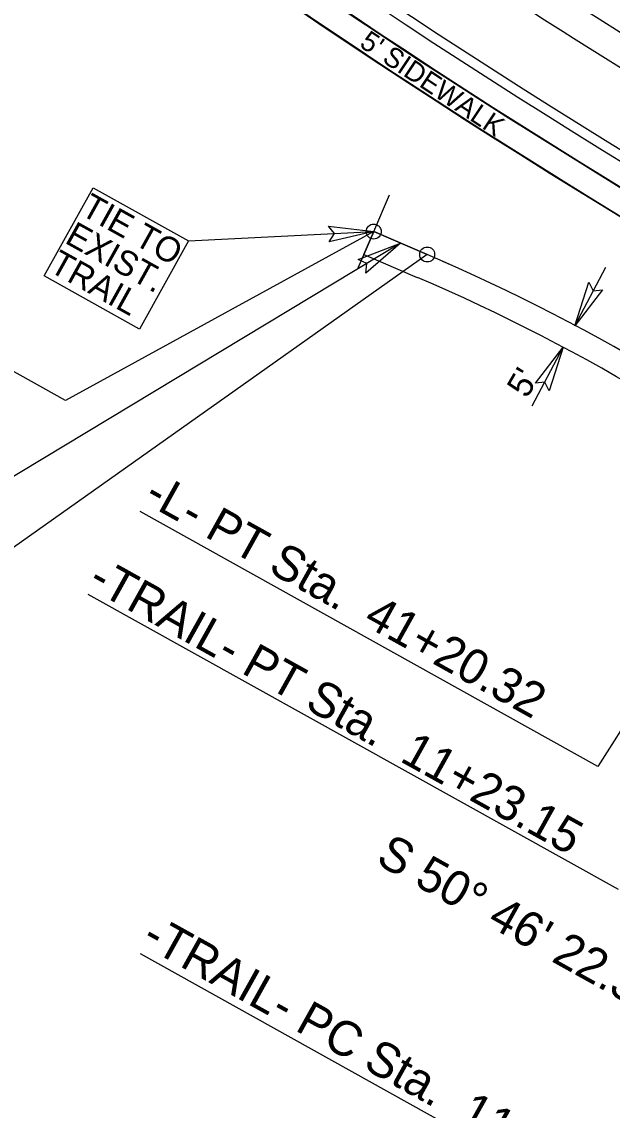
# Model space of a CAD drawing. Extents: x 1762196 to 1766326, y 709922 to 713142.
# Drawn here: x 1764380.6 to 1764499.2, y 710792.5 to 711011.1 of the extents above; entities that cross this region are included whole.
import ezdxf

# ---------------------------------------------------------------- set-up
doc = ezdxf.new("R2010")
doc.units = 0
for name, color, linetype in [('Pattern 1', 7, 'Continuous'), ('Pattern 2', 7, 'Continuous'), ('Prop Conc 2ft 6in Curb and Gutter', 7, 'Continuous'), ('Prop Dimension', 7, 'Continuous'), ('Prop EOT', 7, 'Continuous'), ('Prop Horizontal Alignment', 7, 'Continuous'), ('Prop Horizontal Alignment Direction Label', 7, 'Continuous'), ('Prop Horizontal Alignment Station Label', 7, 'Continuous'), ('Prop Horizontal Alignment Tick Large', 7, 'Continuous'), ('Prop Lane Lines', 7, 'Continuous'), ('Prop Terminator CELL', 7, 'Continuous')]:
    doc.layers.add(name, color=color, linetype=linetype)

msp = doc.modelspace()

# ---------------------------------------------------------------- linework, layer by layer
at = {"layer": 'Pattern 1'}
for p, q in [((1764451.28, 710968.95), (1764449.3, 710964.35)), ((1764462.01, 710964.34), (1764451.28, 710968.95)), ((1764449.3, 710964.35), (1764460.03, 710959.74))]:
    msp.add_line(p, q, dxfattribs=at)
for centre, radius, start, end in [((1765296.46, 712280.56), 1468.5, 220.01407, 240.8436), ((1765296.46, 712280.56), 1473.5, 220.01407, 240.8436), ((1765306.57, 712293.87), 1543.05, 224.81689, 240.93056), ((1765306.57, 712293.87), 1548.05, 224.8166, 240.93028), ((1764304.05, 710596.85), 400, 50.7729, 66.7403), ((1764304.05, 710596.85), 395, 50.7729, 66.7403)]:
    msp.add_arc(centre, radius, start, end, dxfattribs=at)
at = {"layer": 'Pattern 2'}
for p, q in [((1764449.3, 710964.35), (1764451.28, 710968.95)), ((1764451.28, 710968.95), (1764462.01, 710964.34)), ((1764449.3, 710964.35), (1764460.03, 710959.74)), ((1764465.06, 710963.03), (1764466.6, 710962.36)), ((1764460.03, 710959.74), (1764460.03, 710959.74))]:
    msp.add_line(p, q, dxfattribs=at)
for centre, radius, start, end in [((1765296.46, 712280.56), 1468.5, 220.01407, 240.8436), ((1765296.46, 712280.56), 1473.5, 220.01407, 240.8436), ((1765296.46, 712280.56), 1526.5, 224.72992, 240.8436), ((1765296.46, 712280.56), 1531.5, 224.72992, 240.8436), ((1764304.05, 710596.85), 400, 50.7729, 66.7403), ((1764304.05, 710596.85), 395, 50.7729, 66.7403)]:
    msp.add_arc(centre, radius, start, end, dxfattribs=at)
at = {"layer": 'Prop Conc 2ft 6in Curb and Gutter'}
for radius, start in [(1478, 220.01407), (1522, 224.72992)]:
    msp.add_arc((1765296.46, 712280.56), radius, start, 240.8436, dxfattribs=at)
at = {"layer": 'Prop Dimension'}
for p, q in [((1764414.09, 710967.05), (1764451.28, 710968.95)), ((1764491.63, 710950.04), (1764497.88, 710961.81)), ((1764483.07, 710933.93), (1764489.32, 710945.7))]:
    msp.add_line(p, q, dxfattribs=at)
msp.add_lwpolyline([(1764394.95, 710977.71), (1764414.09, 710967.05), (1764404.25, 710949.37), (1764385.11, 710960.03)], close=True, dxfattribs=at)
at = {"layer": 'Prop EOT'}
for radius, start in [(1480, 220.01407), (1520, 224.72992)]:
    msp.add_arc((1765296.46, 712280.56), radius, start, 240.8436, dxfattribs=at)
at = {"layer": 'Prop Horizontal Alignment'}
msp.add_line((1764462.01, 710964.34), (1764451.28, 710968.95), dxfattribs=at)
for centre, radius, start, end in [((1765296.46, 712280.56), 1500, 216.32502, 240.8436), ((1764304.05, 710596.85), 400, 50.7729, 66.7403)]:
    msp.add_arc(centre, radius, start, end, dxfattribs=at)
at = {"layer": 'Prop Horizontal Alignment Station Label'}
for p, q in [((1764389.43, 710935.03), (1764273.03, 710999.86)), ((1764566.4, 710971.93), (1764496.28, 710861.52)), ((1764451.28, 710968.95), (1764389.43, 710935.03)), ((1764456.64, 710966.64), (1764357.72, 710906.93)), ((1764462.01, 710964.34), (1764346.9, 710882.83)), ((1764496.28, 710861.52), (1764404.38, 710912.69)), ((1764500.44, 710836.76), (1764393.94, 710896.06)), ((1764509.01, 710765.62), (1764404.47, 710823.84))]:
    msp.add_line(p, q, dxfattribs=at)
for centre in [(1764451.28, 710968.95), (1764462.01, 710964.34)]:
    msp.add_circle(centre, 1.5, dxfattribs=at)
at = {"layer": 'Prop Horizontal Alignment Tick Large'}
for q in [(1764454.44, 710976.3), (1764448.12, 710961.6)]:
    msp.add_line((1764451.28, 710968.95), q, dxfattribs=at)
at = {"layer": 'Prop Lane Lines'}
for radius, start in [(1494, 222.11492), (1506, 234.71999)]:
    msp.add_arc((1765296.46, 712280.56), radius, start, 240.8436, dxfattribs=at)
at = {"layer": 'Prop Terminator CELL'}
for points in [[(1764442.21, 710970.04), (1764451.28, 710968.95), (1764442.32, 710966.89), (1764443.39, 710968.55)], [(1764448.14, 710963.32), (1764456.64, 710966.64), (1764449.72, 710960.6), (1764449.88, 710962.56)], [(1764497.22, 710957.26), (1764491.63, 710950.04), (1764494.46, 710958.79), (1764495.33, 710957.02)], [(1764483.73, 710938.48), (1764489.32, 710945.7), (1764486.49, 710936.96), (1764485.62, 710938.72)]]:
    msp.add_lwpolyline(points, close=True, dxfattribs=at)

# ---------------------------------------------------------------- texts
at = {"layer": 'Prop Dimension'}
for s, height, rotation, p in [("5' SIDEWALK", 4, 326.2975, (1764448.21, 711006.22)), ('TIE TO', 5, 330.9251, (1764392.19, 710972.46)), ('EXIST.', 5, 330.9251, (1764389.03, 710966.77)), ('TRAIL', 5, 330.9251, (1764385.87, 710961.09)), ("5'", 5, 59.6469, (1764482.05, 710935.27))]:
    msp.add_text(s, height=height, rotation=rotation, dxfattribs=at).set_placement(p)
at = {"layer": 'Prop Horizontal Alignment Direction Label'}
msp.add_text('S 50%%d 46\' 22.3" E', height=7, rotation=330.8875, dxfattribs=at).set_placement((1764451.44, 710842.13))
at = {"layer": 'Prop Horizontal Alignment Station Label'}
for s, p in [('-L- PT Sta.  41+20.32', (1764404.85, 710914.62)), ('-TRAIL- PT Sta.  11+23.15', (1764393.58, 710897.59)), ('-TRAIL- PC Sta.  11+85.47', (1764404.37, 710825.8))]:
    msp.add_text(s, height=7, rotation=330.8875, dxfattribs=at).set_placement(p)

doc.saveas('drawing.dxf')
